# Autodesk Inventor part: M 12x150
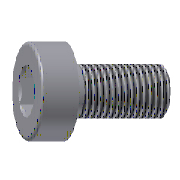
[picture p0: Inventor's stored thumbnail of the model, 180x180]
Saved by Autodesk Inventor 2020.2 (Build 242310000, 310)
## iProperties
Manager: www.cadconsulting.pl
Company: Fabian Stasiak CAD Consulting
Created: 2014-02
Part Number: M 12x150
Material: Stal, miękka
Description: Socket Head Cap Screw DIN 912 - 12.9
Document SubType Name: Modeling
Designer: F.Stasiak
Standard Revision: 1
Manufacturer: DME
Language: pl-PL
Size Designation: 12x150
Categories: <MemberInstance><Categories><Category DisplayName="Forma wtryskowa" InternalName="349578f2-f4d4-4954-8c09-8e99297a61c0" Mnemonic="MOLD"><Category DisplayName="C
Mass: 0.133121 g
Surface Area: 2.01441 cm^2
Volume: 0.133121 cm^3
Density: 7.85 g/cm^3
Appearance: Częściowo polerowana
Catalog Web Link: www.expertbooks.pl
IsCustomPart: 0
Author: F.Stasiak
Subject: Zbiór ćwiczeń. Autodesk Inventor 2020. Kurs Professional
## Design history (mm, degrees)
sketch "Sketch1"
  geometry: L1 (0, -182.4)-(0, 44.4) reference; L2 (5.774, 12)-(9, 12); L3 (9, 12)-(9, 0); L4 (9, 0)-(6, 0); L5 (6, 0)-(6, -150); L6 (6, -150)-(0, -150); L7 (0, 2.996)-(0, -150); L8 (0, 2.996)-(5, 6); L9 (5, 6)-(5, 11.226); L10 (5, 11.226)-(5.774, 12); 1 further point
  constraints: 18 end point, 4 vertical, 3 horizontal, 2 point on line
  dimensions: "d0" = 18 diameter of L3 L1 (= dk); "d1" = 12 distance between parallel lines of L4 L2 (= k); "d2" = 12 diameter of L5 L1 (= d); "d3" = 150 distance between parallel lines of L6 L4 (= L); "d4" = 59 deg angle of L1 L8; "d5" = 45 deg angle of L1 L10; "d6" = 10 diameter of L9 L1 (= sw); "d7" = 11.54701 diameter of L2.start L1 (= 1.1547 x sw); "d8" = 6 distance from line of L8.end L2 (= t)
revolve "Revolution1" sketch "Sketch1" stored, may be unused: angle "d44" = 90 deg
sketch "Sketch2"
  geometry: L1 (0, 5.774)-(5, 2.887); L2 (5, 2.887)-(5, -2.887); L3 (5, -2.887)-(0, -5.774); L4 (0, -5.774)-(-5, -2.887); L5 (-5, -2.887)-(-5, 2.887); L6 (-5, 2.887)-(0, 5.774); 3 further points
  constraints: 12 end point, 2 vertical alignment, 1 coincident, 14 other
extrude "Extrusion1" cut sketch "Sketch2" taper "d9" = 0 deg; stored distance "d45" = 10
thread "Thread1" dims "d10" = 28 (= b), "d11" = 0
chamfer "Chamfer1" distance "d12" = 0.875 (= 0.5 x P); stored, may be unused: second distance "d50" = 2, angle "d51" = 45 deg
fillet "Fillet1" dims "d13" = 0.875 (= 0.5 x P)
body "Solid1"
other parameters: "d" = 12 [user parameter; used in 1 equation term], "L" = 150 [user parameter; used in 1 equation term], "dk" = 18 [user parameter; used in 1 equation term], "b" = 28 [user parameter; used in 1 equation term], "k" = 12 [user parameter; used in 1 equation term], "sw" = 10 [user parameter; used in 2 equation terms], "t" = 6 [user parameter; used in 1 equation term], "P" = 1.75 [user parameter; used in 2 equation terms], "d14" = 0, "d15" = 0, "d55" = 0
